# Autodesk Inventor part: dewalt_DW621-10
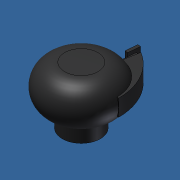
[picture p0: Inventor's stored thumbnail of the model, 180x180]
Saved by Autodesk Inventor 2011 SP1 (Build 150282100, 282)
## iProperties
Created: 2011-02
Part Number: dewalt_DW621-10
Material: Gummi
Catalog Web Link: www.mittelmeyer.de
Document SubType Name: Modellieren
Designer: TMT
Manufacturer: Standard
Standards Organization: Custom
Density: 0.93 g/cm^3
Author: TMT
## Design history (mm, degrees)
sketch "Skizze2"
  geometry: C1 r 31.5 at (0, 0); 1 further point
  constraints: 1 centre point, 1 coincident
  dimensions: "d5" = 63 diameter of C1 (= durchmesser_01)
extrude "Extrusion2" new body sketch "Skizze2" distance "d6" = 35 (= hoehe_01); taper "d7" = 0 deg
fillet "Rundung3" dims "d8" = 17.5
sketch "Skizze3"
  geometry: C1 r 14 at (0, 0) reference; C2 r 16 at (0, 0)
  constraints: 1 centre point, 1 coincident
  dimensions: "d9" = 32 diameter of C2
extrude "Extrusion3" join sketch "Skizze3" distance "d10" = 13; taper "d11" = 0 deg
workplane "Arbeitsebene1"
sketch "Skizze4"
  geometry: L1 (-44.1, 0)-(44.1, 0) reference; L2 (0, -44.1)-(0, 44.1) reference; L3 (31.5, 0)-(31.5, 29.105); L4 (0, 0)-(7.528, 42.691); L5 (0, 0)-(31.5, 0); C1 r 14 at (0, 0) reference; C2 r 14 at (0, 0) reference; A1 r 50 centre (-18.5, 0) between (31.5, 0) and (7.528, 42.691); 1 further point
  constraints: 6 end point, 2 point on circle, 2 point on line, 1 centre point, 1 collinear, 1 horizontal alignment, 1 parallel, 1 vertical, 1 other
  dimensions: "d14" = 10 deg angle of L4 L2; "d15" = 100 diameter of A1
extrude "Extrusion4" join sketch "Skizze4" stored distance "d16" = 14; taper "d17" = 0 deg
sketch "Skizze5"
  geometry: L1 (7.528, 42.691)-(5.216, 29.583) reference; L2 (0, 0)-(3.755, 42.921); L3 (0, 0)-(29.848, 0); A1 r 50 centre (-18.5, 0) between (31.5, 0) and (7.528, 42.691) reference; A2 r 48.348 centre (-18.5, 0) between (29.848, 0) and (3.755, 42.921)
  constraints: 4 end point, 2 point on circle, 1 centre point, 1 coincident, 1 horizontal
  dimensions: "d18" = 1.65243 radial gap between concentric circles of A1 A2; "d19" = 85 deg angle of L3 L2
extrude "Extrusion5" join sketch "Skizze5" stored distance "d20" = 10; taper "d21" = 0 deg
sketch "Skizze6"
  geometry: L1 (5, 16.771)-(5, 29.085) reference; L2 (5, 29.085)-(-5, 29.085) reference; L3 (-5, 29.085)-(-5, 16.771) reference; L4 (-8, 22.085)-(8, 22.085); L5 (8, 22.085)-(8, 32.085); L6 (8, 32.085)-(-8, 32.085); L7 (-8, 32.085)-(-8, 22.085); 1 further point
  constraints: 8 end point, 2 parallel, 1 horizontal, 1 perpendicular
  dimensions: "d22" = 3 distance between parallel lines of L7 L3; "d23" = 3 distance between parallel lines of L5 L1 (= d22); "d24" = 3 distance between parallel lines of L6 L2; "d25" = 10 distance of L6.end L4.start
extrude "Extrusion6" join sketch "Skizze6" distance "d26" = 2.5; taper "d27" = 0 deg
node "Volumenkörper1"
node "Volumenkörpern"
node "Oberflächenkörpern"
node "Projizierte Kontur1"
other parameters: "durchmesser_01" = 63 [user parameter; used in 1 equation term], "hoehe_01" = 35 [user parameter; used in 1 equation term], "d12" = -17.5
